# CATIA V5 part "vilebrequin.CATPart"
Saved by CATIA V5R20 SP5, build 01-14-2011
Part number: vilebrequin
Bounding box of the stored display mesh (mm): x -20.885 to 20.885, y -25 to 22.952, z -72 to -5
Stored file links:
  F:\Catia_finish\vilebrequin.CATPart
  F:\Catia_finish\ASS_compresseur.CATProduct
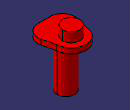
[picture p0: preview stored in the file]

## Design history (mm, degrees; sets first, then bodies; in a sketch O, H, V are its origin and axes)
External parameters (linked from other documents)
  External.excentricite_vilebrequin = 6 mm
Set1
  Point1: linked copy from another document
  Point2: linked copy from another document
Body1 (main body)
  Sketch1 on xy-plane, origin (0, 0, 0), H (1, 0, 0), V (0, 1, 0)
    point P1 (-17, 6)
    line L1 (-17, 6) -> (-25, -25)
    point P2 (-25, -25)
    line L2 (-25, -25) -> (25, -25)
    line L3 (25, -25) -> (17, 6)
    point P4 (17, 6)
    point P5 (0, 6)
    axis line L4 (0, 55) -> (0, -7.2144)
    arc A1 centre (0, 6) radius 17 from (17, 6) to (-17, 6) ccw
    reference projected point E1 (0, 6) from Point1
    length L2 = 50
    distance L4 P2 = 25
    distance P5 L2 = 31 {= External.excentricite_vilebrequin +25mm}
    distance P4 L2 = 31 {= External.excentricite_vilebrequin +25mm}
    distance P1 L2 = 31 {= External.excentricite_vilebrequin +25mm}
    horizontal: L2 H
    perpendicularity: L4 L2
    coincidence: P5 L4, P5 E1
  Pad1: profile Sketch1, direction (0, 0, 1), length -16, opposite side length 22
  Sketch2 on end face of Pad1, origin (0, 0, -16), H (1, 0, 0), V (0, 1, 0)
    circle A1 centre (0, 6) radius 10
    point P1 (0, 6)
    reference projected point E1 (0, 6) from Point1
    radius A1 = 10
    coincidence: E1 P1
  Pad2: profile Sketch2, direction (0, 0, 1), length 11
  Fillet1: radius 14, on edge [face of Pad1 from Sketch1.L3 | face of Pad1 from Sketch1.L2]; edge [face of Pad1 from Sketch1.L2 | face of Pad1 from Sketch1.L1]
  Sketch3 on start face of Pad1, origin (0, 0, -22), H (1, 0, 0), V (0, -1, 0)
    circle A1 centre (0, 0) radius 10
    point P1 (0, 0)
    reference projected point E1 (0, 0) from Point2
    radius A1 = 10
    coincidence: P1 E1
  Pad3: profile Sketch3, direction (0, 0, -1), length 50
